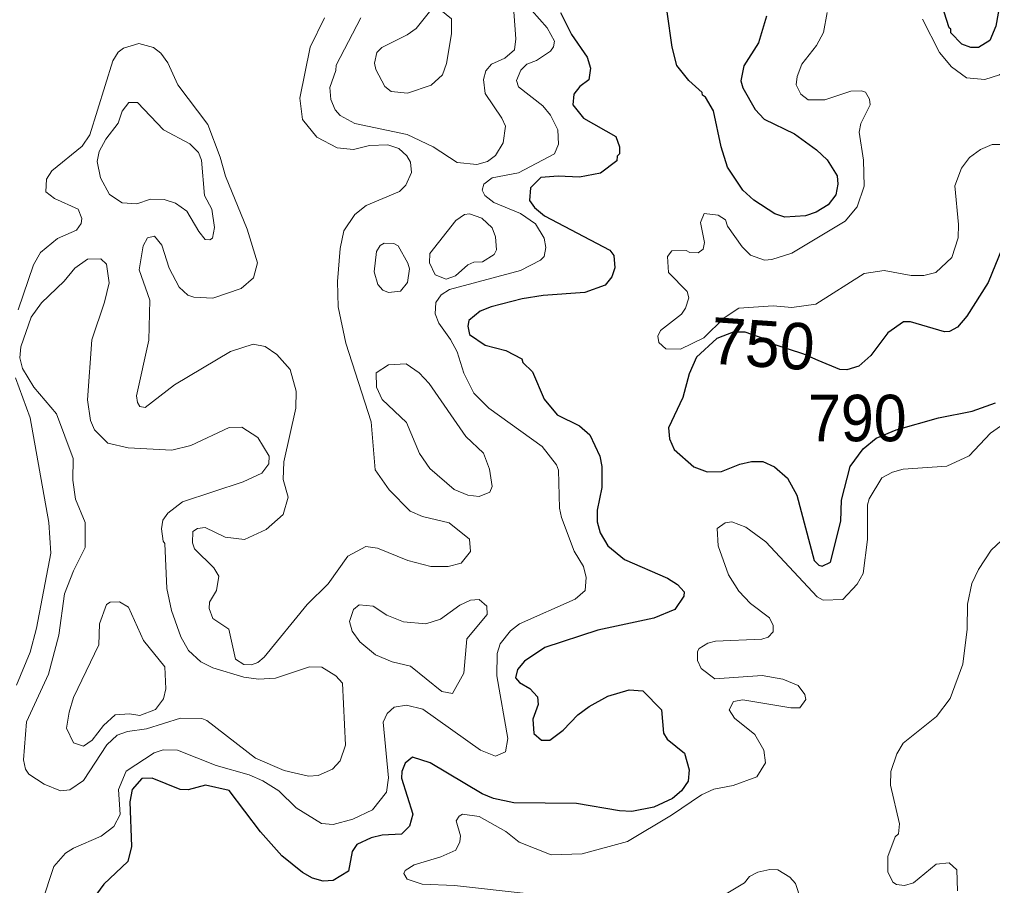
# Model space of a CAD drawing. Extents: x 763.2 to 816.8, y 7896.5 to 7952.7.
# Drawn here: x 771.35 to 774.699, y 7919.723 to 7922.705 of the extents above; entities that cross this region are included whole.
import ezdxf
from ezdxf.enums import TextEntityAlignment as Align

# ---------------------------------------------------------------- set-up
doc = ezdxf.new("R2010")
doc.units = 0
doc.header["$LTSCALE"] = 0.064
doc.layers.add('1', color=7, linetype='Continuous', lineweight=25)
doc.layers.add('2', color=7, linetype='Continuous', lineweight=13)
doc.layers.add('21', color=7, linetype='Continuous')
doc.layers.add('61', color=7, linetype='Continuous')

msp = doc.modelspace()

# ---------------------------------------------------------------- linework, layer by layer
at = {"layer": '1'}
for points in [[(774.7266, 7922.7712), (774.7106, 7922.6816), (774.6893, 7922.6326), (774.651, 7922.6085), (774.6241, 7922.6079), (774.5931, 7922.6195)], [(773.2119, 7922.7288), (773.2497, 7922.653), (773.3033, 7922.5747), (773.315, 7922.5373), (773.3097, 7922.4974), (773.2789, 7922.4743), (773.2577, 7922.448)], [(773.9213, 7922.7161), (773.8933, 7922.6241), (773.8427, 7922.5451), (773.8328, 7922.4938), (773.8393, 7922.4695), (773.8817, 7922.3951), (773.9134, 7922.3613), (774.0174, 7922.3113), (774.0933, 7922.2563), (774.1295, 7922.2218), (774.1643, 7922.1659), (774.1662, 7922.1375), (774.1595, 7922.1015), (774.1333, 7922.0671), (774.0913, 7922.0411), (774.0555, 7922.029), (773.9838, 7922.0243), (773.9494, 7922.0351), (773.8777, 7922.0829), (773.8398, 7922.1176), (773.7867, 7922.1968), (773.7644, 7922.266), (773.7389, 7922.3903), (773.7113, 7922.4376), (773.7003, 7922.4446), (773.7, 7922.4538), (773.6536, 7922.4942), (773.6125, 7922.546), (773.5957, 7922.6092), (773.5793, 7922.7306)], [(774.5931, 7922.6195), (774.5549, 7922.6591), (774.5553, 7922.6713), (774.5492, 7922.6758), (774.5327, 7922.73)], [(773.2577, 7922.448), (773.2544, 7922.4113), (773.2909, 7922.3652), (773.4019, 7922.3016), (773.4149, 7922.2665), (773.4151, 7922.2419)], [(773.4151, 7922.2419), (773.4072, 7922.2338), (773.4058, 7922.2185), (773.3495, 7922.1755), (773.2772, 7922.1623), (773.2042, 7922.1655), (773.1445, 7922.1607), (773.1086, 7922.1248), (773.105, 7922.0818), (773.1223, 7922.0577), (773.1573, 7922.0292), (773.3822, 7921.9105), (773.3955, 7921.8918), (773.3989, 7921.8499), (773.3887, 7921.8189), (773.3661, 7921.7899), (773.2962, 7921.7646), (773.1523, 7921.7546), (773.08, 7921.7431), (772.9732, 7921.7157), (772.9354, 7921.7002), (772.8961, 7921.6689), (772.8931, 7921.6485), (772.8991, 7921.6207), (772.9526, 7921.5836), (773.0241, 7921.5655), (773.0791, 7921.5363), (773.0823, 7921.5243), (773.1151, 7921.4916), (773.1557, 7921.3981), (773.2007, 7921.3435), (773.2778, 7921.3054), (773.3124, 7921.275), (773.3475, 7921.2015), (773.3543, 7921.1654), (773.3545, 7921.094), (773.3384, 7921.0152), (773.3381, 7920.9748), (773.3482, 7920.9373), (773.3751, 7920.8928), (773.4317, 7920.8459), (773.5796, 7920.7817), (773.615, 7920.7591), (773.6371, 7920.7343), (773.6365, 7920.7196), (773.6051, 7920.673), (773.5335, 7920.6437), (773.3404, 7920.6027), (773.1582, 7920.5429), (773.0882, 7920.4956), (773.0644, 7920.4668), (773.0575, 7920.4384), (773.0713, 7920.4224), (773.1067, 7920.4014), (773.1325, 7920.3733), (773.1355, 7920.3465), (773.1162, 7920.2962), (773.1197, 7920.2462), (773.1462, 7920.2233), (773.1751, 7920.2232), (773.2212, 7920.2577), (773.2721, 7920.3112), (773.3107, 7920.34), (773.3743, 7920.3749), (773.4482, 7920.397), (773.4951, 7920.3938), (773.5596, 7920.328), (773.5666, 7920.2482), (773.5794, 7920.2269), (773.6392, 7920.1787), (773.6548, 7920.1211), (773.6513, 7920.0827), (773.6287, 7920.0488), (773.5978, 7920.0233), (773.5328, 7919.9927), (773.4579, 7919.9784), (773.4145, 7919.9799), (773.2666, 7920.006), (773.0512, 7920.0076), (772.9811, 7920.0232), (772.9419, 7920.0389), (772.7637, 7920.1459), (772.7026, 7920.1653), (772.6772, 7920.1449), (772.666, 7920.1161), (772.6644, 7920.0925), (772.7034, 7919.969), (772.6927, 7919.9275), (772.6647, 7919.8996), (772.5984, 7919.8971), (772.5599, 7919.8874), (772.5106, 7919.8646), (772.4948, 7919.8408), (772.4827, 7919.7723), (772.4298, 7919.7402)], [(774.7316, 7921.9174), (774.6839, 7921.7991), (774.6103, 7921.6836), (774.578, 7921.6458), (774.5508, 7921.63), (774.5335, 7921.6298), (774.4162, 7921.6638), (774.3925, 7921.6633), (774.3389, 7921.6264), (774.2795, 7921.5476), (774.2384, 7921.5111), (774.1969, 7921.4983), (774.1729, 7921.4998), (774.0987, 7921.5306), (774.0495, 7921.5524), (773.9467, 7921.5856), (773.9167, 7921.6046), (773.8471, 7921.6283), (773.806, 7921.6283), (773.7498, 7921.6068), (773.6799, 7921.5422), (773.6548, 7921.4844), (773.6335, 7921.4039), (773.5839, 7921.2991), (773.5876, 7921.2616), (773.6027, 7921.224), (773.671, 7921.1652), (773.7169, 7921.1469), (773.7663, 7921.1481), (773.8287, 7921.1741), (773.8696, 7921.1827), (773.9082, 7921.1825), (773.9483, 7921.1641), (773.9932, 7921.1255), (774.0257, 7921.0676), (774.0854, 7920.8424), (774.1012, 7920.8261), (774.1128, 7920.8232), (774.1413, 7920.8363), (774.1772, 7920.9775), (774.1791, 7921.0499), (774.2085, 7921.1661), (774.2532, 7921.227), (774.2984, 7921.2635), (774.3677, 7921.2926), (774.513, 7921.3339), (774.6283, 7921.3561), (774.7095, 7921.3846)], [(772.1798, 7919.9084), (772.0716, 7920.0505), (771.9902, 7920.0683), (771.9303, 7920.0523), (771.9024, 7920.0537), (771.8065, 7920.0924), (771.7705, 7920.092), (771.7376, 7920.0535), (771.7296, 7920.0111), (771.7355, 7919.8572), (771.7225, 7919.806), (771.6404, 7919.7282), (771.6153, 7919.6938)], [(772.4298, 7919.7402), (772.3947, 7919.7382), (772.3585, 7919.7491), (772.3239, 7919.7684), (772.2527, 7919.8259), (772.1798, 7919.9084)]]:
    msp.add_lwpolyline(points, dxfattribs=at)
at = {"layer": '2'}
for points in [[(772.5248, 7922.7107), (772.4395, 7922.547), (772.4389, 7922.5295), (772.4179, 7922.4702), (772.4212, 7922.4295), (772.4359, 7922.394), (772.4538, 7922.3744), (772.504, 7922.3466), (772.6845, 7922.3092), (772.7737, 7922.266), (772.8564, 7922.2118), (772.9236, 7922.2053), (772.961, 7922.2163), (772.9881, 7922.2367), (773.0144, 7922.2796), (773.0224, 7922.3369), (773.0105, 7922.3649), (772.9522, 7922.4496), (772.947, 7922.4985), (772.9551, 7922.5281), (772.9745, 7922.551), (773.0202, 7922.5711), (773.0535, 7922.6001), (773.0586, 7922.6378), (773.0488, 7922.7627)], [(772.856, 7921.56), (772.8334, 7921.6034), (772.7935, 7921.6589), (772.7808, 7921.6912), (772.7827, 7921.7309), (772.8016, 7921.7572), (772.8295, 7921.7757), (773.0747, 7921.8406), (773.1428, 7921.8756), (773.1557, 7921.8892), (773.1619, 7921.92), (773.1558, 7921.9522), (773.1257, 7922.0008), (773.0743, 7922.0372), (772.9827, 7922.0747), (772.9517, 7922.0988), (772.9422, 7922.1173), (772.9475, 7922.1381), (772.9769, 7922.1598), (773.0675, 7922.1772), (773.1918, 7922.2417), (773.2045, 7922.275), (773.2033, 7922.3244), (773.1777, 7922.3755), (773.1509, 7922.4071), (773.0671, 7922.4725), (773.0605, 7922.4951), (773.0754, 7922.5304), (773.0957, 7922.5508), (773.1293, 7922.5632), (773.1773, 7922.5951), (773.1882, 7922.6109), (773.1917, 7922.6305), (773.1661, 7922.6756), (773.1129, 7922.7358)], [(774.4572, 7922.7063), (774.5164, 7922.5912), (774.558, 7922.5414), (774.6087, 7922.5043), (774.6723, 7922.4976), (774.7233, 7922.5141), (774.7929, 7922.5645), (774.8568, 7922.6012), (774.8873, 7922.6341), (774.9076, 7922.6904), (774.9139, 7922.7594)], [(772.4, 7922.7106), (772.3509, 7922.6089), (772.3144, 7922.4333), (772.3239, 7922.3602), (772.3728, 7922.2992), (772.4434, 7922.2633), (772.5, 7922.2576), (772.5548, 7922.2706), (772.6174, 7922.2737), (772.6556, 7922.2602)], [(774.4184, 7921.8237), (774.3257, 7921.84), (774.2569, 7921.8301), (774.0911, 7921.7249), (774.0076, 7921.7136), (773.9434, 7921.7185), (773.8257, 7921.7104), (773.7757, 7921.678), (773.705, 7921.6088), (773.6244, 7921.5695), (773.5746, 7921.5704), (773.5503, 7921.5924), (773.547, 7921.6141), (773.5566, 7921.6344), (773.6282, 7921.6901), (773.642, 7921.7104), (773.6532, 7921.7464), (773.648, 7921.7681), (773.5831, 7921.834), (773.5798, 7921.8892), (773.5951, 7921.9078), (773.644, 7921.9091), (773.6567, 7921.9024), (773.6852, 7921.9009), (773.7025, 7921.9143), (773.7077, 7921.9365), (773.6932, 7922.006), (773.7061, 7922.0364), (773.7547, 7922.0313), (773.7794, 7922.0144), (773.7866, 7921.9936), (773.8367, 7921.922), (773.8659, 7921.8929), (773.9136, 7921.8765), (773.9389, 7921.8781), (774.0083, 7921.9), (774.192, 7922.0103), (774.2325, 7922.0598), (774.2565, 7922.131), (774.2552, 7922.2205), (774.2403, 7922.3168), (774.2451, 7922.3471), (774.2778, 7922.4103), (774.2759, 7922.4305), (774.2616, 7922.4542), (774.2481, 7922.4596), (774.2114, 7922.4577), (774.1212, 7922.4284), (774.0647, 7922.4285), (774.0385, 7922.4477), (774.0235, 7922.4801), (774.0265, 7922.5083), (774.043, 7922.5512), (774.0931, 7922.6155), (774.1166, 7922.6595), (774.13, 7922.7285)], [(772.6577, 7922.1129), (772.5432, 7922.0643), (772.5039, 7922.033), (772.4657, 7921.9771), (772.4537, 7921.9159), (772.444, 7921.8023), (772.4471, 7921.7149), (772.4729, 7921.5909), (772.5605, 7921.3191), (772.5742, 7921.1545), (772.6219, 7921.0853), (772.6949, 7921.0122), (772.7373, 7920.9942), (772.8282, 7920.9717), (772.8992, 7920.9151), (772.9024, 7920.8735), (772.8706, 7920.8328), (772.825, 7920.8214), (772.7651, 7920.8212), (772.6862, 7920.8424), (772.582, 7920.8849), (772.5421, 7920.8901), (772.48, 7920.8567), (772.4126, 7920.7622), (772.3396, 7920.6902), (772.1916, 7920.5097), (772.17, 7920.4914), (772.1486, 7920.4827), (772.1225, 7920.4847), (772.0933, 7920.502), (772.0705, 7920.6057), (772.0152, 7920.6424), (772.0023, 7920.6769), (772.004, 7920.6983), (772.0285, 7920.7387), (772.0361, 7920.788), (772.0194, 7920.8167), (771.9527, 7920.8821), (771.9455, 7920.9028), (771.9462, 7920.942), (771.9622, 7920.9519), (771.989, 7920.9558), (772.0584, 7920.923), (772.124, 7920.915), (772.1995, 7920.9485), (772.2573, 7921.0008), (772.2743, 7921.0603), (772.2569, 7921.1213), (772.2592, 7921.1818), (772.3005, 7921.3663), (772.3025, 7921.425), (772.281, 7921.5002), (772.2357, 7921.5518), (772.1952, 7921.5789), (772.1542, 7921.5869), (772.0765, 7921.5615), (771.883, 7921.4468), (771.7829, 7921.3692), (771.7646, 7921.3728), (771.7557, 7921.3859), (771.7522, 7921.4092), (771.7948, 7921.6011), (771.798, 7921.7385), (771.7621, 7921.8424), (771.7754, 7921.9253), (771.7901, 7921.9533), (771.8147, 7921.9585), (771.8402, 7921.9282), (771.8653, 7921.849), (771.8996, 7921.7836), (771.9299, 7921.7559), (771.9504, 7921.7486), (772.0159, 7921.745), (772.113, 7921.7789), (772.1559, 7921.815), (772.1695, 7921.8674), (772.1335, 7921.9824), (772.0589, 7922.1652), (772.0411, 7922.2302), (771.9977, 7922.3426), (771.8947, 7922.48), (771.8604, 7922.555), (771.8369, 7922.5882), (771.8115, 7922.6079), (771.7609, 7922.6219), (771.7074, 7922.6064), (771.6899, 7922.5927), (771.6707, 7922.5622), (771.5919, 7922.3072), (771.5653, 7922.2682), (771.4617, 7922.1839), (771.4434, 7922.1555), (771.4404, 7922.111), (771.4702, 7922.0879), (771.5522, 7922.0511)], [(774.8337, 7922.274), (774.6971, 7922.2739), (774.6578, 7922.2575), (774.6199, 7922.2295), (774.5918, 7922.1929), (774.5693, 7922.1324), (774.582, 7921.9988)], [(772.6556, 7922.2602), (772.6833, 7922.235), (772.6953, 7922.2132), (772.6987, 7922.1777), (772.6793, 7922.1346), (772.6577, 7922.1129)], [(771.5522, 7922.0511), (771.5644, 7922.0199), (771.5626, 7922.0025), (771.546, 7921.9796), (771.4813, 7921.951), (771.4223, 7921.9024)], [(774.582, 7921.9988), (774.5802, 7921.9531), (774.5591, 7921.8853), (774.5041, 7921.8338), (774.4622, 7921.8237), (774.4184, 7921.8237)], [(771.4223, 7921.9024), (771.3985, 7921.8603), (771.3457, 7921.7046)], [(773.1982, 7921.1712), (773.1484, 7921.2341), (772.9655, 7921.3663), (772.914, 7921.4178), (772.8795, 7921.4868), (772.856, 7921.56)], [(771.3359, 7921.4713), (771.387, 7921.3331), (771.4513, 7920.9734), (771.4578, 7920.8677), (771.4086, 7920.6098), (771.387, 7920.5264), (771.3398, 7920.4125)], [(772.8656, 7919.874), (772.8678, 7919.8945), (772.8534, 7919.9462), (772.8629, 7919.9626), (772.8748, 7919.9694), (772.9323, 7919.9613), (773.0235, 7919.9094), (773.0701, 7919.8731), (773.1793, 7919.8286), (773.2863, 7919.8319), (773.4429, 7919.8752), (773.5939, 7919.9652), (773.6969, 7920.0351), (773.74, 7920.055), (773.8059, 7920.0673), (773.8875, 7920.0973), (773.9179, 7920.146), (773.9112, 7920.1891), (773.881, 7920.2433), (773.8109, 7920.2992), (773.7927, 7920.3283), (773.8077, 7920.3564), (773.8392, 7920.3625), (774.0043, 7920.3347), (774.0351, 7920.3347), (774.0561, 7920.364), (774.0528, 7920.3804), (774.0301, 7920.4114), (773.9767, 7920.4335), (773.9065, 7920.4465), (773.7435, 7920.435), (773.6956, 7920.4708), (773.6834, 7920.4975), (773.6835, 7920.5292), (773.6889, 7920.5391), (773.7195, 7920.5574), (773.7455, 7920.5647), (773.9049, 7920.5713), (773.9265, 7920.5786), (773.9438, 7920.5968), (773.9442, 7920.6189), (773.9315, 7920.6447), (773.8656, 7920.6947), (773.8256, 7920.7361), (773.7903, 7920.7926), (773.7544, 7920.8927), (773.7515, 7920.9518), (773.7789, 7920.9715), (773.8016, 7920.9754), (773.8492, 7920.9575), (773.9181, 7920.9066), (774.0956, 7920.7175), (774.1155, 7920.7058), (774.1836, 7920.7077), (774.2326, 7920.7606), (774.2532, 7920.7973), (774.2681, 7920.9149), (774.2689, 7921.0336), (774.2739, 7921.0543), (774.3181, 7921.1271), (774.3546, 7921.1462), (774.3914, 7921.1564), (774.5417, 7921.1669), (774.6187, 7921.203), (774.6914, 7921.2804), (774.822, 7921.3718)], [(771.4269, 7919.6633), (771.4686, 7919.7893), (771.5086, 7919.8349), (771.5354, 7919.8524), (771.6316, 7919.8933), (771.6744, 7919.9267), (771.6959, 7919.9676), (771.6913, 7920.0536), (771.7167, 7920.1166), (771.8135, 7920.1804), (771.8448, 7920.19), (771.8941, 7920.1898), (772.0263, 7920.137), (772.1406, 7920.1044), (772.1872, 7920.0842), (772.242, 7920.0495), (772.302, 7919.9904), (772.3891, 7919.9373), (772.4291, 7919.9337), (772.4969, 7919.9513), (772.5644, 7919.9834), (772.613, 7920.0444), (772.6197, 7920.0945), (772.6018, 7920.2857), (772.6155, 7920.3158), (772.6389, 7920.3373), (772.6816, 7920.3445), (772.7376, 7920.3306), (772.9363, 7920.1896), (772.9884, 7920.1688), (773.0231, 7920.1834), (773.0308, 7920.2298), (772.9929, 7920.4455), (772.994, 7920.5226), (773.0045, 7920.5549), (773.0401, 7920.6004), (773.0708, 7920.6243), (773.2626, 7920.7091), (773.2972, 7920.7387), (773.2999, 7920.784), (773.2907, 7920.8214), (773.2595, 7920.8749), (773.2149, 7920.9898), (773.2083, 7921.0227), (773.2048, 7921.1533), (773.1982, 7921.1712)], [(774.764, 7920.9427), (774.6946, 7920.8774), (774.6503, 7920.811), (774.6279, 7920.7629)], [(774.6279, 7920.7629), (774.613, 7920.6921), (774.6116, 7920.6058), (774.5971, 7920.4856), (774.5526, 7920.3666), (774.5064, 7920.3051)], [(774.5064, 7920.3051), (774.3915, 7920.2129), (774.3696, 7920.177), (774.3488, 7920.1154), (774.3474, 7920.0687), (774.3782, 7919.936), (774.3749, 7919.9016), (774.3636, 7919.8907), (774.3389, 7919.8237), (774.3389, 7919.7706), (774.356, 7919.7347), (774.3683, 7919.7263), (774.3955, 7919.7235), (774.4271, 7919.7323), (774.5045, 7919.7973), (774.55, 7919.802), (774.5757, 7919.7776), (774.5786, 7919.7049)], [(772.6727, 7919.765), (772.6769, 7919.7751), (772.7085, 7919.794), (772.8006, 7919.822), (772.852, 7919.8453), (772.8656, 7919.874)], [(773.0839, 7919.6966), (772.8466, 7919.7233), (772.7357, 7919.7283), (772.6839, 7919.7457), (772.6727, 7919.765)], [(774.057, 7919.6183), (774.0207, 7919.7301), (774.0007, 7919.7524), (773.9598, 7919.7777), (773.932, 7919.7789), (773.8912, 7919.769), (773.8629, 7919.7545), (773.8452, 7919.7328), (773.7708, 7919.6876)]]:
    msp.add_lwpolyline(points, dxfattribs=at)
for points in [[(772.5803, 7922.5908), (772.5968, 7922.6085), (772.6843, 7922.6518), (772.7149, 7922.6738), (772.7609, 7922.7312), (772.8006, 7922.7373), (772.8367, 7922.7069), (772.8369, 7922.655), (772.8196, 7922.5528), (772.8062, 7922.5144), (772.7671, 7922.4791), (772.6854, 7922.4515), (772.6295, 7922.4567), (772.6072, 7922.4739), (772.5769, 7922.5327), (772.5722, 7922.5543)], [(771.8475, 7922.0845), (771.8868, 7922.0718), (771.9262, 7922.0453), (771.9669, 7921.9746), (771.9893, 7921.9474), (772.0056, 7921.9457), (772.0144, 7921.9516), (772.0216, 7921.9889), (772.0117, 7922.0514), (771.9871, 7922.0992), (771.9767, 7922.2208), (771.9658, 7922.2471), (771.9366, 7922.2766), (771.8451, 7922.3244), (771.7559, 7922.4185), (771.7258, 7922.4183), (771.7035, 7922.3886), (771.6892, 7922.3474), (771.6466, 7922.293), (771.6242, 7922.25), (771.6176, 7922.2158), (771.6291, 7922.1599), (771.6596, 7922.1021), (771.7035, 7922.0733), (771.754, 7922.0702), (771.8014, 7922.0864)], [(772.8516, 7922.0125), (772.8814, 7922.0338), (772.8984, 7922.0353), (772.9414, 7922.0211), (772.977, 7921.9869), (772.988, 7921.956), (772.9911, 7921.9115), (772.9838, 7921.8954), (772.9438, 7921.8701), (772.9141, 7921.8694), (772.8933, 7921.8598), (772.8505, 7921.8225), (772.8181, 7921.8108), (772.7807, 7921.8259), (772.7614, 7921.8674), (772.7617, 7921.8995)], [(772.5833, 7921.7922), (772.5708, 7921.8356), (772.5792, 7921.9055), (772.591, 7921.9262), (772.6047, 7921.9351), (772.6383, 7921.9339), (772.6528, 7921.9251), (772.6869, 7921.8653), (772.6919, 7921.8461), (772.6855, 7921.7997), (772.6616, 7921.7694), (772.6205, 7921.7646), (772.5999, 7921.7732)], [(771.3991, 7921.4386), (771.3607, 7921.5026), (771.3515, 7921.5396), (771.3549, 7921.5778), (771.3903, 7921.6801), (771.4252, 7921.7298), (771.5034, 7921.8035), (771.5403, 7921.8484), (771.5845, 7921.8794), (771.6297, 7921.8811), (771.65, 7921.8623), (771.6581, 7921.7984), (771.643, 7921.7311), (771.5993, 7921.6018), (771.5844, 7921.3958), (771.5948, 7921.3244), (771.6079, 7921.2924), (771.6536, 7921.2458), (771.7245, 7921.2306), (771.8744, 7921.2222), (771.9394, 7921.2386), (772.0716, 7921.2995), (772.1156, 7921.3007), (772.1699, 7921.2661), (772.2089, 7921.201), (772.2086, 7921.1746), (772.1836, 7921.1431), (772.1198, 7921.1129), (771.9112, 7921.0436), (771.8607, 7921.0052), (771.8435, 7920.9812), (771.8392, 7920.9514), (771.8442, 7920.9092), (771.8507, 7920.9011), (771.8574, 7920.746), (771.8734, 7920.6697), (771.9047, 7920.5789), (771.9322, 7920.5322), (771.9745, 7920.4933), (772.0158, 7920.473), (772.1222, 7920.4402), (772.1722, 7920.4334), (772.231, 7920.4371), (772.3485, 7920.476), (772.3908, 7920.4745), (772.439, 7920.4448), (772.4618, 7920.4199), (772.4719, 7920.2062), (772.4538, 7920.1524), (772.4272, 7920.1241), (772.3779, 7920.1019), (772.3451, 7920.0998), (772.2609, 7920.1197), (772.1617, 7920.1614), (771.9942, 7920.2914), (771.9774, 7920.2985), (771.9044, 7920.2998), (771.7871, 7920.263), (771.7214, 7920.253), (771.6858, 7920.2406), (771.6501, 7920.2081), (771.5698, 7920.0848), (771.5233, 7920.0526), (771.4915, 7920.049), (771.4353, 7920.0724), (771.3825, 7920.1066), (771.3706, 7920.1237), (771.3643, 7920.1555), (771.374, 7920.2864), (771.4493, 7920.4508), (771.4855, 7920.5855), (771.5048, 7920.7273), (771.5354, 7920.8069), (771.5756, 7920.8873), (771.5756, 7920.9729), (771.5433, 7921.0536), (771.5335, 7921.1193), (771.5347, 7921.1936), (771.4768, 7921.3466)], [(772.7601, 7921.4518), (772.725, 7921.4882), (772.6808, 7921.5192), (772.6199, 7921.5163), (772.5776, 7921.4886), (772.5784, 7921.4392), (772.5978, 7921.3969), (772.6818, 7921.3176), (772.7267, 7921.2103), (772.762, 7921.1592), (772.8461, 7921.0861), (772.8928, 7921.0669), (772.932, 7921.063), (772.9691, 7921.0776), (772.9762, 7921.0965), (772.968, 7921.1566), (772.9467, 7921.212), (772.8856, 7921.2687)], [(771.5204, 7920.3206), (771.5359, 7920.3704), (771.6233, 7920.552), (771.6254, 7920.6242), (771.6497, 7920.6904), (771.6615, 7920.6984), (771.6946, 7920.7003), (771.7247, 7920.6821), (771.777, 7920.5666), (771.8501, 7920.4763), (771.8539, 7920.4002), (771.8453, 7920.3656), (771.8185, 7920.3288), (771.7641, 7920.3083), (771.729, 7920.3149), (771.6792, 7920.311), (771.6391, 7920.2743), (771.6003, 7920.2242), (771.5706, 7920.2034), (771.5354, 7920.2149), (771.5123, 7920.2654)], [(772.7483, 7920.6242), (772.7994, 7920.6397), (772.8652, 7920.6884), (772.9025, 7920.7061), (772.9325, 7920.7079), (772.9582, 7920.6855), (772.96, 7920.6564), (772.89, 7920.572), (772.8792, 7920.4549), (772.8403, 7920.3845), (772.8034, 7920.3911), (772.696, 7920.4787), (772.6328, 7920.4935), (772.5755, 7920.5178), (772.5218, 7920.5627), (772.495, 7920.599), (772.4852, 7920.6326), (772.4998, 7920.673), (772.5185, 7920.6894), (772.5673, 7920.6846), (772.6146, 7920.6539), (772.6711, 7920.631)]]:
    msp.add_lwpolyline(points, close=True, dxfattribs=at)

# ---------------------------------------------------------------- texts
at = {"layer": '21', "width": 0.95}
msp.add_text('790', height=0.16, dxfattribs=at).set_placement((774.0638, 7921.2527))
at = {"layer": '61'}
msp.add_text('750', height=0.16, rotation=356.096, dxfattribs=at).set_placement((773.9025, 7921.5084), align=Align.CENTER)

doc.saveas('drawing.dxf')
